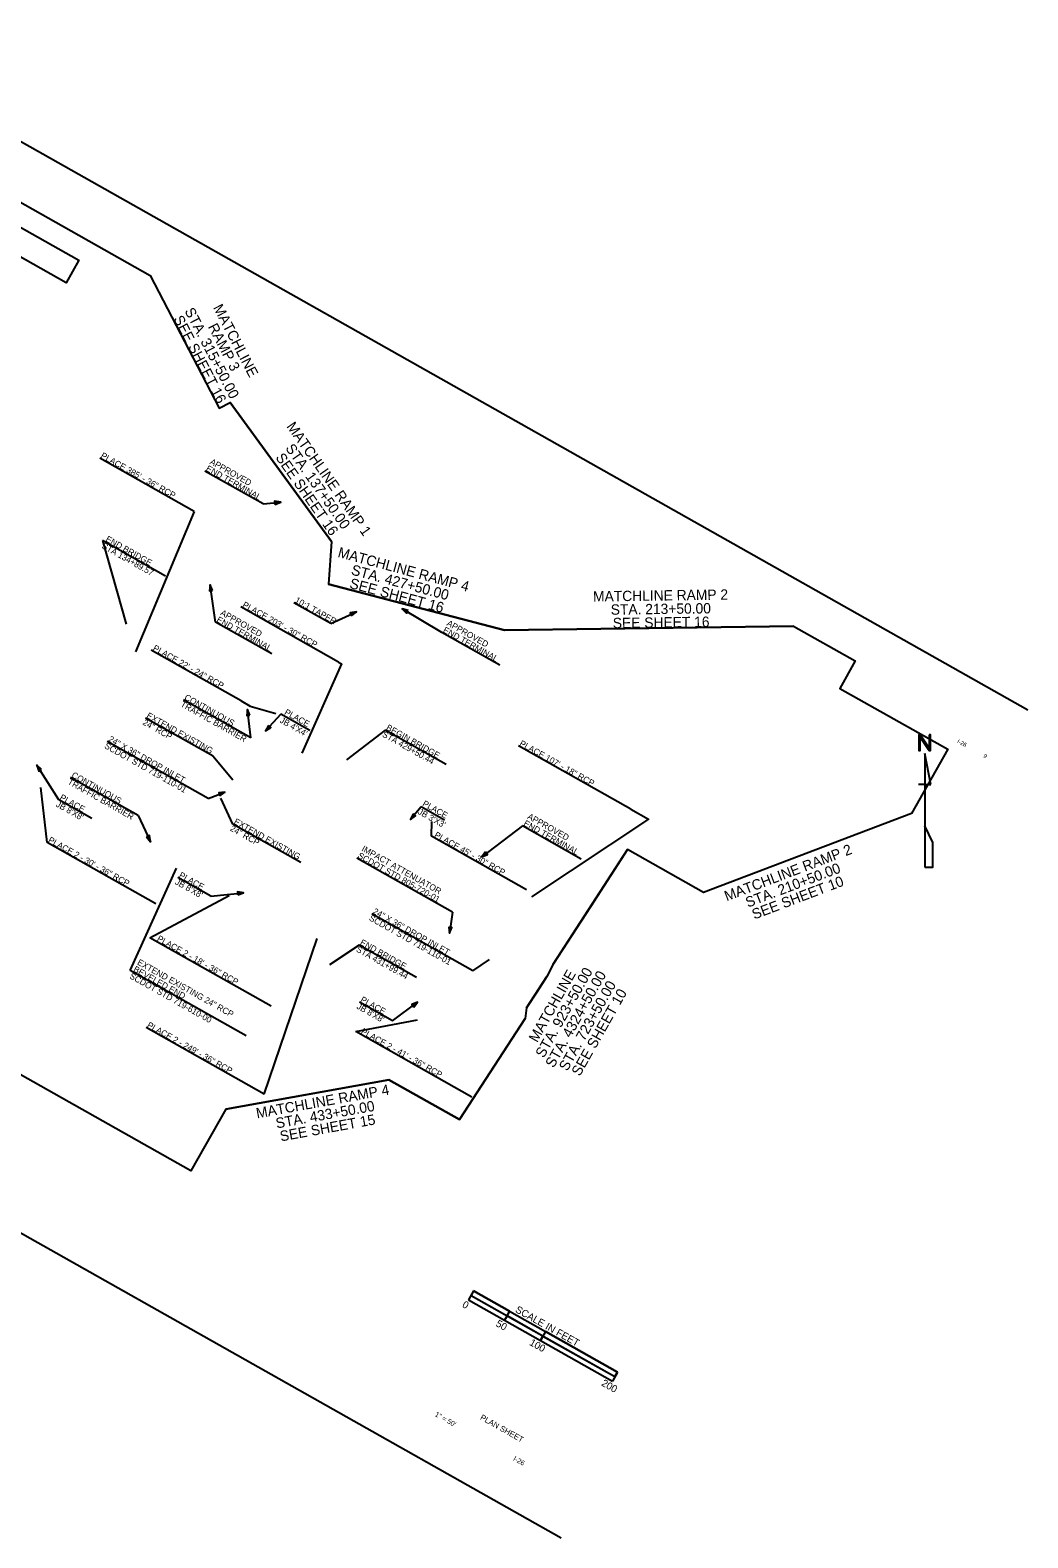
# Model space of a CAD drawing. Extents: x 2220413 to 2222436, y 468301 to 470126.
# Drawn here: x 2221229 to 2222436, y 468301 to 470126 of the extents above; entities that cross this region are included whole.
import ezdxf

# ---------------------------------------------------------------- set-up
doc = ezdxf.new("R2010")
doc.units = 0
for name, color, linetype in [('Default', 7, 'Continuous'), ('North Arrow', 7, 'Continuous'), ('RD_HY_Misc', 7, 'Continuous'), ('RD_PD_Final_TX', 7, 'Continuous'), ('RD_SHT_MatchLine', 7, 'Continuous'), ('RD_SHT_ShtClip', 7, 'Continuous'), ('RD_SHT_TX', 7, 'Continuous')]:
    doc.layers.add(name, color=color, linetype=linetype)

msp = doc.modelspace()

# ---------------------------------------------------------------- linework, layer by layer
at = {"layer": 'Default'}
msp.add_line((2221667.3, 468927), (2221627.4, 468949.6), dxfattribs=at)
msp.add_lwpolyline([(2221667.3, 468927), (2221697.7, 468949.4)], dxfattribs=at)
msp.add_lwpolyline([(2221693, 468943.5), (2221697.7, 468949.4), (2221690.7, 468946.6)], close=True, dxfattribs=at)
at = {"layer": 'North Arrow'}
for p, q in [((2222311.6, 469250.3), (2222311.6, 469212.8)), ((2222319.1, 469212.8), (2222311.6, 469250.3)), ((2222311.6, 469212.8), (2222304.1, 469212.8)), ((2222311.6, 469212.8), (2222311.6, 469162.8)), ((2222311.6, 469212.8), (2222319.1, 469212.8)), ((2222311.6, 469162.8), (2222311.6, 469112.8))]:
    msp.add_line(p, q, dxfattribs=at)
for points in [[(2222304.5, 469256.7), (2222304.5, 469254), (2222306.2, 469254), (2222306.2, 469256.7), (2222306.2, 469270.2), (2222308.1, 469270.2), (2222306.4, 469272.9), (2222304.5, 469272.9), (2222304.5, 469270.2)], [(2222315, 469256.7), (2222316.8, 469254), (2222318.7, 469254), (2222318.7, 469256.7), (2222317, 469256.7), (2222308.1, 469270.2), (2222306.2, 469270.2)], [(2222317, 469272.9), (2222317, 469256.7), (2222318.7, 469256.7), (2222318.7, 469272.9)]]:
    msp.add_lwpolyline(points, close=True, dxfattribs=at)
msp.add_lwpolyline([(2222311.6, 469112.8), (2222321.6, 469112.8), (2222321.6, 469142.8), (2222311.6, 469162.8)], dxfattribs=at)
at = {"layer": 'RD_HY_Misc'}
for p, q in [((2221427.3, 469543.4), (2221312.9, 469608)), ((2221602, 469361), (2221483.6, 469427.8)), ((2221484.1, 469314), (2221375.2, 469375.4)), ((2221450.4, 469247), (2221368.3, 469293.3)), ((2221567.2, 469278.3), (2221532.3, 469297.9)), ((2221444.2, 469196), (2221322.1, 469264.9)), ((2221955.7, 469182.9), (2221819.8, 469259.5)), ((2221303.2, 469171.7), (2221263.3, 469194.2)), ((2221730.3, 469169.9), (2221702, 469185.9)), ((2221556.3, 469118.7), (2221474.2, 469165)), ((2221380.7, 469068.6), (2221249.3, 469142.7)), ((2221829.6, 469085.3), (2221714.4, 469150.3)), ((2221447.5, 469077.7), (2221407.6, 469100.2)), ((2221764.4, 468987.6), (2221642.3, 469056.4)), ((2221520.6, 468944.7), (2221373.8, 469027.5)), ((2221490.3, 468908.6), (2221350, 468987.8)), ((2221512, 468838), (2221369, 468918.7)), ((2221763.5, 468834.7), (2221623.1, 468913.9))]:
    msp.add_line(p, q, dxfattribs=at)
for points in [[(2221427.3, 469543.4), (2221356.1, 469373.5)], [(2221602, 469361), (2221605.6, 469359), (2221557.6, 469251)], [(2221484.1, 469314), (2221495.2, 469307.7), (2221526.1, 469298.9)], [(2221532.3, 469297.9), (2221513.6, 469277.7)], [(2221263.3, 469194.2), (2221236.9, 469236.1)], [(2221450.4, 469247), (2221473.9, 469218.4)], [(2221249.3, 469142.7), (2221241.7, 469209.3)], [(2221444.2, 469196), (2221464.4, 469203.6)], [(2221474.2, 469165), (2221459.6, 469196.3)], [(2221702, 469185.9), (2221689, 469170.6)], [(2221955.7, 469182.9), (2221977.1, 469170.8), (2221835.7, 469076.8)], [(2221714.4, 469150.3), (2221715, 469168)], [(2221350, 468987.8), (2221405.7, 469111.7)], [(2221373.8, 469027.5), (2221469.6, 469078.6)], [(2221447.5, 469077.7), (2221487, 469082)], [(2221512, 468838), (2221576.1, 469026.4)], [(2221764.4, 468987.6), (2221784.9, 469001)], [(2221623.1, 468913.9), (2221697.6, 468928.1)]]:
    msp.add_lwpolyline(points, dxfattribs=at)
for points in [[(2221517.1, 469284.3), (2221513.6, 469277.7), (2221519.9, 469281.7)], [(2221242.4, 469231), (2221236.9, 469236.1), (2221239.1, 469229)], [(2221458.3, 469199.3), (2221464.4, 469203.6), (2221457, 469202.9)], [(2221692.2, 469177.4), (2221689, 469170.6), (2221695.1, 469174.8)], [(2221480, 469079.3), (2221487, 469082), (2221479.6, 469083.1)]]:
    msp.add_lwpolyline(points, close=True, dxfattribs=at)
at = {"layer": 'RD_PD_Final_TX'}
for p, q in [((2221510.7, 469552.5), (2221440.3, 469592.2)), ((2221392.5, 469465.2), (2221316.4, 469508.2)), ((2221592.6, 469407.7), (2221547.9, 469432.9)), ((2221521.2, 469371), (2221453.2, 469409.4)), ((2221797.3, 469357.2), (2221727.2, 469396.8)), ((2221495.9, 469269.3), (2221414.2, 469315.3)), ((2221732.2, 469237), (2221658.4, 469278.7)), ((2221359.3, 469175.3), (2221277.6, 469221.4)), ((2221895.9, 469122.7), (2221824.7, 469162.8)), ((2221739.8, 469058.5), (2221624, 469123.9)), ((2221696.5, 468979.3), (2221626.8, 469018.6))]:
    msp.add_line(p, q, dxfattribs=at)
for points in [[(2221510.7, 469552.5), (2221532, 469554.4)], [(2221316.4, 469508.2), (2221344.9, 469407)], [(2221453.2, 469409.4), (2221446.6, 469454.5)], [(2221592.6, 469407.7), (2221623.6, 469421.9)], [(2221727.2, 469396.8), (2221679, 469425.5)], [(2221495.9, 469269.3), (2221492, 469303.8)], [(2221658.4, 469278.7), (2221611.5, 469242.6)], [(2221359.3, 469175.3), (2221374.5, 469143.7)], [(2221824.7, 469162.8), (2221775.5, 469125.4)], [(2221739.8, 469058.5), (2221736.4, 469032.9)], [(2221626.8, 469018.6), (2221591.2, 468994.8)]]:
    msp.add_lwpolyline(points, dxfattribs=at)
for points in [[(2221524.9, 469551.8), (2221532, 469554.4), (2221524.6, 469555.7)], [(2221449.5, 469447.6), (2221446.6, 469454.5), (2221445.7, 469447.1)], [(2221617.9, 469417.1), (2221623.6, 469421.9), (2221616.2, 469420.6)], [(2221686.2, 469423.5), (2221679, 469425.5), (2221684.2, 469420.1)], [(2221494.8, 469296.8), (2221492, 469303.8), (2221490.9, 469296.4)], [(2221369.6, 469149.4), (2221374.5, 469143.7), (2221373.1, 469151)], [(2221780.1, 469131.4), (2221775.5, 469125.4), (2221782.4, 469128.3)], [(2221735.4, 469040.4), (2221736.4, 469032.9), (2221739.3, 469039.9)]]:
    msp.add_lwpolyline(points, close=True, dxfattribs=at)
at = {"layer": 'RD_SHT_MatchLine'}
for p, q in [((2221374.2, 469828.9), (2221457.6, 469668.2)), ((2221457.6, 469668.2), (2221471, 469675.1)), ((2221593.4, 469506.8), (2221471, 469675.1)), ((2221593.4, 469506.8), (2221590, 469455.3)), ((2221803.1, 469399.5), (2221590, 469455.3)), ((2222152.8, 469404.5), (2221803.1, 469399.5)), ((2222295.6, 469177.9), (2222043.7, 469082.4)), ((2221862, 468995.5), (2221952, 469134.1)), ((2222043.7, 469082.4), (2221952, 469134.1)), ((2221829.7, 468942.5), (2221854.3, 468980.4)), ((2221862, 468995.5), (2221854.3, 468980.4)), ((2221829.7, 468942.5), (2221827.8, 468929.8)), ((2221748.3, 468807.4), (2221827.8, 468929.8)), ((2221465.5, 468820), (2221663, 468855.5)), ((2221663, 468855.5), (2221748.3, 468807.4))]:
    msp.add_line(p, q, dxfattribs=at)
at = {"layer": 'RD_SHT_ShtClip'}
msp.add_lwpolyline([(2221043.3, 470015.5), (2221374.2, 469828.9), (2221457.6, 469668.2), (2221471, 469675.1), (2221593.4, 469506.8), (2221590, 469455.3), (2221803.1, 469399.5), (2222152.8, 469404.5), (2222227.5, 469362.4), (2222208.8, 469329.2), (2222339.4, 469255.5), (2222295.6, 469177.9), (2222043.7, 469082.4), (2221952, 469134.1), (2221907, 469064.8), (2221862, 468995.5), (2221854.3, 468980.4), (2221842, 468961.4), (2221829.7, 468942.5), (2221827.8, 468929.8), (2221748.3, 468807.4), (2221663, 468855.5), (2221465.5, 468820), (2221423.4, 468745.3), (2220746.6, 469127.1)], dxfattribs=at)
at = {"layer": 'RD_SHT_TX'}
for p, q in [((2222436.4, 469302.8), (2220977.6, 470125.8)), ((2220412.5, 469124.2), (2221871.4, 468301.2)), ((2221765.5, 468600), (2221759.4, 468589.1)), ((2221765.5, 468600), (2221762.4, 468594.6)), ((2221765.5, 468600), (2221939.7, 468501.8)), ((2221809, 468575.5), (2221765.5, 468600)), ((2221759.4, 468589.1), (2221933.5, 468490.9)), ((2221762.4, 468594.6), (2221936.6, 468496.3)), ((2221762.4, 468594.6), (2221806, 468570)), ((2221809, 468575.5), (2221802.9, 468564.6)), ((2221806, 468570), (2221802.9, 468564.6)), ((2221802.9, 468564.6), (2221846.4, 468540)), ((2221806, 468570), (2221809, 468575.5)), ((2221849.5, 468545.4), (2221806, 468570)), ((2221852.6, 468550.9), (2221846.4, 468540)), ((2221846.4, 468540), (2221849.5, 468545.4)), ((2221852.6, 468550.9), (2221849.5, 468545.4)), ((2221849.5, 468545.4), (2221936.6, 468496.3)), ((2221939.7, 468501.8), (2221852.6, 468550.9)), ((2221939.7, 468501.8), (2221933.5, 468490.9)), ((2221936.6, 468496.3), (2221939.7, 468501.8))]:
    msp.add_line(p, q, dxfattribs=at)
msp.add_lwpolyline([(2220945.5, 470040.3), (2221287.6, 469847.3), (2221272.3, 469820.2), (2220930.2, 470013.2)], close=True, dxfattribs=at)

# ---------------------------------------------------------------- texts
at = {"layer": 'Default'}
for s, p in [("JB 8'X8'", (2221623.2, 468942.2)), ('PLACE', (2221627.8, 468950.4))]:
    msp.add_text(s, height=7.5, rotation=330.5715, dxfattribs=at).set_placement(p)
at = {"layer": 'RD_HY_Misc'}
for s, p in [('PLACE 385\' - 36" RCP', (2221313.4, 469608.8)), ('PLACE 203\' - 30" RCP', (2221485, 469428.2)), ('PLACE 22\' - 24" RCP', (2221376.6, 469375.8)), ('24" RCP', (2221364.2, 469285.9)), ('EXTEND EXISTING', (2221368.8, 469294.1)), (" JB 4'X4'", (2221527.7, 469289.8)), (' PLACE', (2221533.3, 469299.6)), ('24" X 36" DROP INLET', (2221322.6, 469265.7)), ('SCDOT STD 719-110-01', (2221317.9, 469257.5)), ('PLACE 107\' - 18" RCP', (2221820.3, 469260.4)), ('PLACE', (2221263.8, 469195.1)), ("JB 8'X8'", (2221259.1, 469186.8)), ("JB 3'X3'", (2221697.4, 469177.8)), ('PLACE', (2221702.9, 469187.6)), ('24" RCP', (2221470, 469157.6)), ('EXTEND EXISTING', (2221474.6, 469165.8)), ('PLACE 2 - 30\' - 36" RCP', (2221249.8, 469143.6)), (' PLACE 45\' - 30" RCP', (2221714.8, 469151.1)), ('PLACE', (2221408.1, 469101)), ("JB 8'X8'", (2221403.4, 469092.8)), ('SCDOT STD 719-110-01', (2221638.2, 469049.1)), ('24" X 36" DROP INLET', (2221642.8, 469057.3)), ('   PLACE 2 - 18\' - 36" RCP', (2221374.3, 469028.4)), (' EXTEND EXISTING 24" RCP', (2221355.2, 468996.9)), (' SCDOT STD 719-610-00', (2221345.8, 468980.3)), (' BEVELED END', (2221350.5, 468988.6)), ('PLACE 2 - 249\' - 36" RCP ', (2221369.5, 468919.6)), ('  PLACE 2 - 41\' - 36" RCP', (2221623.6, 468914.8))]:
    msp.add_text(s, height=7.5, rotation=330.5715, dxfattribs=at).set_placement(p)
at = {"layer": 'RD_PD_Final_TX'}
for s, p in [('END TERMINAL', (2221440.8, 469593.1)), ('APPROVED', (2221445.5, 469601.3)), (' END BRIDGE', (2221316.9, 469509.1)), (' STA 134+89.57', (2221312.2, 469500.8)), ('10:1 TAPER', (2221548.4, 469433.8)), ('END TERMINAL', (2221453.6, 469410.2)), ('APPROVED', (2221458.3, 469418.5)), ('END TERMINAL', (2221727.7, 469397.6)), ('APPROVED', (2221732.3, 469405.9)), ('TRAFFIC BARRIER', (2221410, 469307.9)), ('CONTINUOUS', (2221414.7, 469316.2)), ('STA 429+50.44', (2221654.2, 469271.3)), ('BEGIN BRIDGE', (2221658.9, 469279.6)), ('TRAFFIC BARRIER', (2221273.4, 469214)), ('CONTINUOUS', (2221278.1, 469222.2)), ('END TERMINAL', (2221825.2, 469163.7)), ('APPROVED', (2221829.9, 469172)), ('SCDOT STD 805-720-01', (2221624.5, 469124.7)), ('IMPACT ATTENUATOR', (2221629.2, 469133)), ('STA 431+99.44', (2221622.7, 469011.2)), ('END BRIDGE', (2221627.3, 469019.5))]:
    msp.add_text(s, height=7.5, rotation=330.5715, dxfattribs=at).set_placement(p)
at = {"layer": 'RD_SHT_MatchLine'}
for s, rotation, p in [('STA. 315+50.00', 297.4295, (2221415.3, 469786.1)), ('MATCHLINE ', 297.4295, (2221449.9, 469790.2)), ('SEE SHEET 16', 297.4295, (2221401.9, 469776.6)), ('RAMP 3 ', 297.4295, (2221443.6, 469767)), ('MATCHLINE RAMP 1', 305.0643, (2221538.5, 469646.2)), ('STA. 137+50.00', 305.0643, (2221537.2, 469619.8)), ('SEE SHEET 16', 305.0643, (2221525.2, 469608.6)), ('MATCHLINE RAMP 4', 344.9842, (2221600.3, 469488.4)), ('STA. 427+50.00', 344.9842, (2221616.5, 469467.2)), ('SEE SHEET 16', 344.9842, (2221614.5, 469450.9)), ('MATCHLINE RAMP 2', 0.8259, (2221910.2, 469434.3)), ('STA. 213+50.00', 0.8259, (2221931.6, 469418.3)), ('SEE SHEET 16', 0.8259, (2221934.1, 469402)), ('MATCHLINE RAMP 2', 20.7664, (2222071.9, 469071.5)), ('STA. 210+50.00', 20.7664, (2222097.5, 469063.8)), ('SEE SHEET 10', 20.7664, (2222105.3, 469049.4)), ('MATCHLINE', 60.5715, (2221842.4, 468899.9)), ('STA. 923+50.00', 60.5715, (2221850.5, 468881.2)), ('STA. 4324+50.00', 60.5715, (2221862.4, 468869.1)), ('STA. 723+50.00', 60.5715, (2221878.9, 468865.2)), ('SEE SHEET 10', 60.5715, (2221894.1, 468859.1)), ('MATCHLINE RAMP 4', 10.2258, (2221503.4, 468808.8)), ('STA. 433+50.00', 10.2258, (2221527.2, 468796.6)), ('SEE SHEET 15', 10.2258, (2221532.2, 468780.9))]:
    msp.add_text(s, height=12.5, rotation=rotation, dxfattribs=at).set_placement(p)
at = {"layer": 'RD_SHT_TX'}
for s, height, p in [('I-26', 5, (2222350.4, 469263.8)), ('9', 5, (2222382, 469246)), ('0', 8.75, (2221750.9, 468581)), ('SCALE IN FEET', 8.75, (2221815.2, 468574.9)), ('50', 8.75, (2221791.6, 468558)), ('100', 8.75, (2221832.3, 468535.1)), ('200', 8.75, (2221919.4, 468486)), ('1" = 50\'', 6, (2221718, 468448.9)), ('PLAN SHEET', 7, (2221772.8, 468444.9)), ('I-26', 6, (2221812.9, 468395.3))]:
    msp.add_text(s, height=height, rotation=330.5715, dxfattribs=at).set_placement(p)

doc.saveas('drawing.dxf')
